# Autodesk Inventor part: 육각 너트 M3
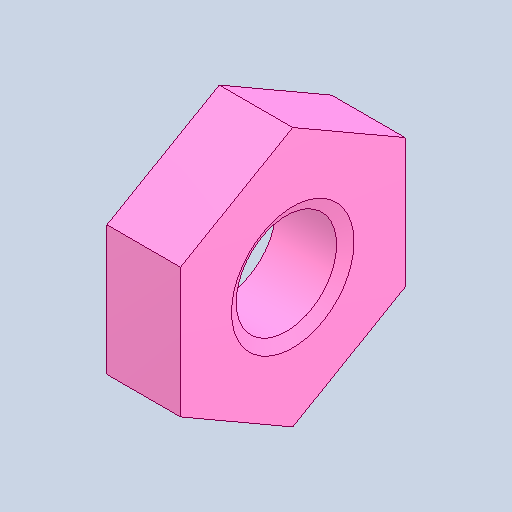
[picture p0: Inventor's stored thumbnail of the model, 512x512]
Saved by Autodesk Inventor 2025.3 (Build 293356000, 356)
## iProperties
Created: 2025-09
Part Number: 육각 너트 M3
Material: 강철, 연강
Description: 6각 너트 및 6각 가는 너트 - 모따기 안된
Document SubType Name: Modeling
Designer: PC-15
Density: 7.85 g/cm^3
Appearance: 기본값
Author: jhkim
Sending System: Autodesk Inventor 2026
Preprocessor: ST-DEVELOPER v20.1
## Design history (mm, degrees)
feature "Solid1"
node "솔리드1"
